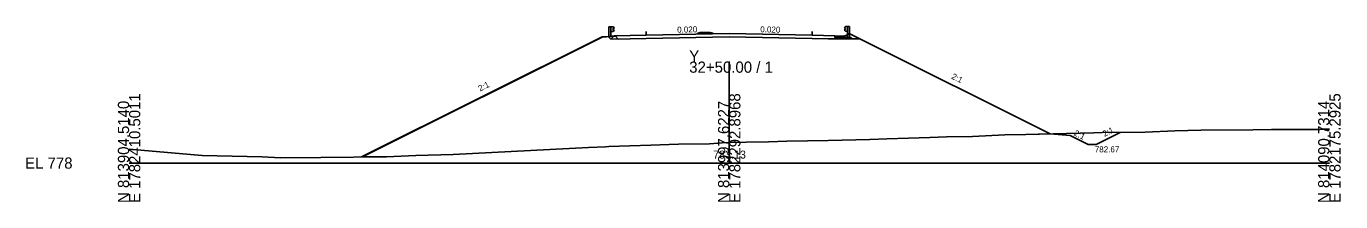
# Model space of a CAD drawing. Extents: x -12583 to 5303, y -44 to 25667.
# Drawn here: x 1974.3 to 2302.8, y 2990.3 to 3034.3 of the extents above; entities that cross this region are included whole.
import ezdxf

# ---------------------------------------------------------------- set-up
doc = ezdxf.new("R2010")
doc.units = 0
for name, color, linetype in [('Exist Cross Section Cell', 7, 'Continuous'), ('Exist XS Center Line Elevation Label', 7, 'Continuous'), ('Exist XS Ground Line', 7, 'Continuous'), ('Prop Conc 5in Monolithic Surface Mount Island', 7, 'Continuous'), ('Prop XS DDE', 7, 'Continuous'), ('Prop XS Ditch Standard Text', 7, 'Continuous'), ('Prop XS Dump Level', 7, 'Continuous'), ('Prop XS Earthwork Shape', 7, 'Continuous'), ('Prop XS EOT Tick Mark', 7, 'Continuous'), ('Prop XS Finish Grade', 7, 'Continuous'), ('Prop XS Finish Grade CurbGutter', 7, 'Continuous'), ('Prop XS Finish Grade Earthwork', 7, 'Continuous'), ('Prop XS Finish Grade Paved Shoulder', 7, 'Continuous'), ('Prop XS Finish Grade Pavement', 7, 'Continuous'), ('Prop XS Guardrail', 7, 'Continuous'), ('Prop XS Pvmt Edge Slope', 7, 'Continuous'), ('Prop XS SE Text', 7, 'Continuous'), ('Prop XS Side Slope Text', 7, 'Continuous'), ('Prop XS Subgrade CurbGutter', 7, 'Continuous'), ('Prop XS Subgrade Earthwork', 7, 'Continuous')]:
    doc.layers.add(name, color=color, linetype=linetype)

msp = doc.modelspace()

# ---------------------------------------------------------------- linework, layer by layer
at = {"layer": 'Exist Cross Section Cell'}
for p, q in [((2150, 3000), (2150, 3025.44)), ((2000, 3000), (2150, 3000)), ((2150, 3000), (2300, 3000))]:
    msp.add_line(p, q, dxfattribs=at)
at = {"layer": 'Exist XS Ground Line'}
for p, q in [((2185.16, 3005.88), (2189.37, 3006.1)), ((2189.37, 3006.1), (2194.78, 3006.26)), ((2194.78, 3006.26), (2200.11, 3006.44)), ((2200.11, 3006.44), (2204.33, 3006.57)), ((2204.33, 3006.57), (2210.79, 3006.65)), ((2210.79, 3006.65), (2218.89, 3007.05)), ((2218.89, 3007.05), (2224.12, 3007.17)), ((2224.12, 3007.17), (2241.1, 3007.59)), ((2241.1, 3007.59), (2243.19, 3007.63)), ((2243.19, 3007.63), (2253.94, 3007.74)), ((2253.94, 3007.74), (2261.36, 3008.1)), ((2261.36, 3008.1), (2267.85, 3008.22)), ((2267.85, 3008.22), (2280.86, 3008.36)), ((2280.86, 3008.36), (2285.54, 3008.38)), ((2285.54, 3008.38), (2295.75, 3008.43)), ((2295.75, 3008.43), (2297.64, 3008.45)), ((2297.64, 3008.45), (2298.43, 3008.46)), ((2298.43, 3008.46), (2300, 3008.48)), ((2000, 3003.49), (2018.29, 3001.86)), ((2081.01, 3002.17), (2114.86, 3003.88)), ((2114.86, 3003.88), (2119.08, 3004.1)), ((2119.08, 3004.1), (2119.95, 3004.15)), ((2119.95, 3004.15), (2130.41, 3004.48)), ((2130.41, 3004.48), (2137.29, 3004.7)), ((2137.29, 3004.7), (2145.09, 3004.85)), ((2145.09, 3004.85), (2148.2, 3005.08)), ((2148.2, 3005.08), (2150, 3005.13)), ((2150, 3005.13), (2154.22, 3005.26)), ((2154.22, 3005.26), (2159.82, 3005.33)), ((2159.82, 3005.33), (2164.42, 3005.48)), ((2164.42, 3005.48), (2174.75, 3005.65)), ((2174.75, 3005.65), (2185.16, 3005.88)), ((2018.29, 3001.86), (2033.23, 3001.59)), ((2033.23, 3001.59), (2037.84, 3001.29)), ((2037.84, 3001.29), (2047.95, 3001.43)), ((2047.95, 3001.43), (2064.37, 3001.59)), ((2064.37, 3001.59), (2071.66, 3001.87)), ((2071.66, 3001.87), (2081.01, 3002.17))]:
    msp.add_line(p, q, dxfattribs=at)
at = {"layer": 'Prop Conc 5in Monolithic Surface Mount Island'}
for p, q in [((2142, 3032.44), (2142.74, 3032.7)), ((2142, 3032.27), (2142, 3032.44)), ((2142.74, 3032.7), (2143.99, 3032.75)), ((2145.24, 3032.75), (2143.99, 3032.75)), ((2146, 3032.52), (2145.24, 3032.75)), ((2146, 3032.35), (2146, 3032.52))]:
    msp.add_line(p, q, dxfattribs=at)
at = {"layer": 'Prop XS DDE'}
for p, q in [((2230.26, 3007.32), (2235.26, 3006.9)), ((2235.26, 3006.9), (2239.72, 3004.67)), ((2247.74, 3007.68), (2241.72, 3004.67)), ((2239.72, 3004.67), (2241.72, 3004.67))]:
    msp.add_line(p, q, dxfattribs=at)
at = {"layer": 'Prop XS Dump Level'}
for p, q in [((2129.25, 3032.01), (2150, 3032.43)), ((2150, 3032.43), (2170.75, 3032.01))]:
    msp.add_line(p, q, dxfattribs=at)
at = {"layer": 'Prop XS Earthwork Shape'}
msp.add_lwpolyline([(2071.66, 3001.87), (2081.01, 3002.17), (2114.86, 3003.88), (2119.08, 3004.1), (2119.95, 3004.15), (2130.41, 3004.48), (2137.29, 3004.7), (2145.09, 3004.85), (2148.2, 3005.08), (2150, 3005.13), (2154.22, 3005.26), (2159.82, 3005.33), (2164.42, 3005.48), (2174.75, 3005.65), (2185.16, 3005.88), (2189.37, 3006.1), (2194.78, 3006.26), (2200.11, 3006.44), (2204.33, 3006.57), (2210.79, 3006.65), (2218.89, 3007.05), (2224.12, 3007.17), (2230.26, 3007.32), (2182.68, 3031.11), (2180.81, 3031.11), (2176.42, 3031.11), (2174.75, 3031.14), (2170.75, 3031.22), (2150, 3031.64), (2129.25, 3031.22), (2125.25, 3031.14), (2122.27, 3031.08), (2121.58, 3031.77), (2118.25, 3031.51), (2058.3, 3001.53), (2064.37, 3001.59)], close=True, dxfattribs=at)
at = {"layer": 'Prop XS EOT Tick Mark'}
for p, q in [((2129.25, 3032.01), (2129.25, 3033.01)), ((2170.75, 3032.01), (2170.75, 3033.01))]:
    msp.add_line(p, q, dxfattribs=at)
at = {"layer": 'Prop XS Finish Grade'}
for p, q in [((2179.44, 3032.15), (2180.02, 3032.44)), ((2182.68, 3031.11), (2180.02, 3032.44)), ((2121.25, 3031.85), (2119.75, 3031.74))]:
    msp.add_line(p, q, dxfattribs=at)
at = {"layer": 'Prop XS Finish Grade CurbGutter'}
for p, q in [((2176.42, 3031.9), (2178.75, 3031.81)), ((2178.75, 3031.81), (2179.44, 3032.15))]:
    msp.add_line(p, q, dxfattribs=at)
at = {"layer": 'Prop XS Finish Grade Earthwork'}
for p, q in [((2118.25, 3031.61), (2058.08, 3001.53)), ((2118.25, 3031.61), (2119.75, 3031.74)), ((2182.68, 3031.11), (2230.26, 3007.32))]:
    msp.add_line(p, q, dxfattribs=at)
at = {"layer": 'Prop XS Finish Grade Paved Shoulder'}
for p, q in [((2129.25, 3032.01), (2121.25, 3031.85)), ((2170.75, 3032.01), (2176.42, 3031.9))]:
    msp.add_line(p, q, dxfattribs=at)
at = {"layer": 'Prop XS Finish Grade Pavement'}
for p, q in [((2129.25, 3032.01), (2150, 3032.43)), ((2150, 3032.43), (2170.75, 3032.01)), ((2150, 3032.43), (2170.75, 3032.01))]:
    msp.add_line(p, q, dxfattribs=at)
at = {"layer": 'Prop XS Guardrail'}
for p, q in [((2119.93, 3034.14), (2120.43, 3034.14)), ((2119.93, 3031.64), (2119.93, 3034.14)), ((2120.43, 3034.14), (2120.93, 3034.14)), ((2120.43, 3034.14), (2120.43, 3031.64)), ((2120.93, 3033.01), (2120.43, 3033.01)), ((2120.93, 3034.14), (2121.22, 3033.94)), ((2121.22, 3033.82), (2120.93, 3033.62)), ((2120.93, 3033.62), (2120.93, 3033.53)), ((2120.93, 3033.53), (2121.22, 3033.33)), ((2121.22, 3033.21), (2120.93, 3033.01)), ((2121.22, 3033.94), (2121.25, 3033.88)), ((2121.25, 3033.88), (2121.22, 3033.82)), ((2121.22, 3033.33), (2121.25, 3033.27)), ((2121.25, 3033.27), (2121.22, 3033.21)), ((2178.78, 3034), (2178.75, 3033.94)), ((2178.75, 3033.94), (2178.78, 3033.88)), ((2178.78, 3033.39), (2178.75, 3033.33)), ((2178.75, 3033.33), (2178.78, 3033.27)), ((2179.07, 3034.2), (2178.78, 3034)), ((2178.78, 3033.88), (2179.07, 3033.68)), ((2179.07, 3033.59), (2178.78, 3033.39)), ((2178.78, 3033.27), (2179.07, 3033.07)), ((2179.57, 3034.2), (2179.07, 3034.2)), ((2179.07, 3033.68), (2179.07, 3033.59)), ((2179.07, 3033.07), (2179.57, 3033.07)), ((2180.07, 3034.2), (2179.57, 3034.2)), ((2179.57, 3034.2), (2179.57, 3031.7)), ((2180.07, 3031.7), (2180.07, 3034.2))]:
    msp.add_line(p, q, dxfattribs=at)
at = {"layer": 'Prop XS Pvmt Edge Slope'}
for p, q in [((2121.25, 3031.85), (2120.44, 3031.05)), ((2179.44, 3031.48), (2180.44, 3031.48)), ((2180.44, 3031.48), (2180.81, 3031.11))]:
    msp.add_line(p, q, dxfattribs=at)
at = {"layer": 'Prop XS Subgrade CurbGutter'}
for p, q in [((2176.42, 3031.9), (2176.42, 3031.48)), ((2176.42, 3031.48), (2179.44, 3031.48)), ((2179.44, 3031.48), (2179.44, 3032.15))]:
    msp.add_line(p, q, dxfattribs=at)
at = {"layer": 'Prop XS Subgrade Earthwork'}
for p, q in [((2120.44, 3031.05), (2119.75, 3031.74)), ((2125.25, 3031.14), (2120.44, 3031.05)), ((2129.25, 3031.22), (2125.25, 3031.14)), ((2150, 3031.64), (2129.25, 3031.22)), ((2170.75, 3031.22), (2150, 3031.64)), ((2170.75, 3031.22), (2174.75, 3031.14)), ((2174.75, 3031.14), (2176.42, 3031.11)), ((2176.42, 3031.11), (2176.42, 3031.11)), ((2176.42, 3031.11), (2180.81, 3031.11)), ((2180.81, 3031.11), (2182.68, 3031.11))]:
    msp.add_line(p, q, dxfattribs=at)

# ---------------------------------------------------------------- texts
at = {"layer": 'Exist Cross Section Cell'}
for s, p in [('Y', (2140, 3025.44)), ('32+50.00 / 1', (2140, 3022.64)), ('EL 778', (1974, 2998.6))]:
    msp.add_text(s, height=2.8, dxfattribs=at).set_placement(p)
for s, p in [('E 1782410.5011', (2002.8, 2990)), ('E 1782292.8968', (2152.8, 2990)), ('E 1782175.2925', (2302.8, 2990)), ('N 813904.5140', (2000, 2990)), ('N 813997.6227', (2150, 2990)), ('N 814090.7314', (2300, 2990))]:
    msp.add_text(s, height=2.8, rotation=90, dxfattribs=at).set_placement(p)
at = {"layer": 'Exist XS Center Line Elevation Label'}
msp.add_text('783.13', height=2, dxfattribs=at).set_placement((2145.99, 3001.13))
at = {"layer": 'Prop XS Ditch Standard Text'}
msp.add_text('782.67', height=1.5, dxfattribs=at).set_placement((2241.37, 3002.69))
at = {"layer": 'Prop XS Dump Level'}
for p in [(2121.25, 3031.71), (2176.42, 3031.86)]:
    msp.add_text('Case2', height=0.04, dxfattribs=at).set_placement(p)
at = {"layer": 'Prop XS SE Text'}
for rotation, p in [(1.1458, (2137, 3032.67)), (358.8542, (2157.75, 3032.77)), (358.8542, (2157.75, 3032.77))]:
    msp.add_text('0.020', height=1.5, rotation=rotation, dxfattribs=at).set_placement(p)
at = {"layer": 'Prop XS Side Slope Text'}
for rotation, p in [(26.5651, (2087.74, 3017.93)), (333.4349, (2205.4, 3021.23)), (333.4349, (2235.99, 3007.03)), (26.5651, (2243.8, 3006.56))]:
    msp.add_text('2:1', height=1.5, rotation=rotation, dxfattribs=at).set_placement(p)

doc.saveas('drawing.dxf')
